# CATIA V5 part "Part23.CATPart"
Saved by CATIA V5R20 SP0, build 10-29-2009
Part number: socket countersunk head screw_din_DIN 7991 - M8 x 20 --- 20N
Revision: ANY
Definition: UNKNOWN
Nomenclature: socket countersunk head screw_din_DIN 7991 - M8 x 20 --- 20N
Source: Unknown
Bounding box of the stored display mesh (mm): x 0 to 20, y -7.59 to 7.59, z -7.785 to 7.785
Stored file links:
  C:\Users\Utente\Desktop\IO LAVORO\3D X SITO CF\CUMSA\3D files GR\GR 344038-10\Part23.CATPart
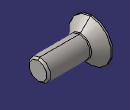
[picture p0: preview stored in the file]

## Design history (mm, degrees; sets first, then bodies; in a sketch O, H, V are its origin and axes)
Body1 "Hex" (main body)
  Solid1: solid without history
